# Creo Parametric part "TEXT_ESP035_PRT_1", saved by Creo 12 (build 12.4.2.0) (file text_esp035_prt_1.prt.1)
Units: Custom; MM, KILOGRAM, SECS

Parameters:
  PTC_WM_ITERATION = "0"
  PTC_WM_VERSION = "-.0"
  PTC_WM_LIFECYCLE_STATE = "In Work"
  PTC_WM_LIFECYCLE = "MO_CADDocument"
  PTC_WM_CREATED_BY = "Maximilian Roepper (Z0017RMS: MO)"
  PTC_WM_CREATED_ON = "18-Sep-26 11:36:42 AM"
  PTC_WM_MODIFIED_BY = "Maximilian Roepper (Z0017RMS: MO)"
  PTC_WM_MODIFIED_ON = "18-Sep-26 11:36:46 AM"
  PDMLINKNUMBER = "PDM000071455000"
  PTC_WM_NAME = "text_esp035_prt_1.prt"
  PTC_WM_NUMBER = "PDM000071455000"

Other parameters: WEIGHT, WEIGHT_FACTOR, WEIGHT_ADD, _MASS_TEMP, _DIFF_TEMP, MC_ERRORS, SUPPLIER

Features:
  1. coordinate system
  2. datum plane "PRT_YZ"
  3. datum plane "PRT_XY"
  4. datum plane "PRT_XZ"
  5. coordinate system
  6. datum axis
  7. datum axis
  8. datum axis
  9. coordinate system
  10. imported feature
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
Other named items: PRT, SIEMENS_MO, DRW_VIEW_ORG, PRT_X, PRT_Y, PRT_Z, CS0, ROUGH_GROB

Layers: 00_STD_CSYS-KSYS, 01_STD_PLANES-EBENEN, 02_STD_AXES-ACHSEN, 03_STD_CSYS-KSYS, 24_IMPORT_FEAT-IMPORT_KE

Surfaces: 6 plane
